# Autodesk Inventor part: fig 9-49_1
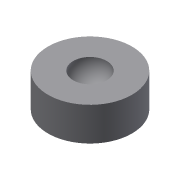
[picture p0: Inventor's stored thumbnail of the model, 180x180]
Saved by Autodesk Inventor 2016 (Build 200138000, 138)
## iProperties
Created: 2013-03
Part Number: fig 9-49_1
Material: Generic
Document SubType Name: Modeling
Designer: CADCIM
Density: 1 g/cm^3
Appearance: Default
Author: CADCIM
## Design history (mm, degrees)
sketch "Sketch1"
  geometry: C1 r 12.5 at (0, 0); 1 further point
  constraints: 1 centre point, 1 coincident
  dimensions: "d0" = 25 diameter of C1
extrude "Extrusion1" new body sketch "Sketch1" distance "d2" = 10; taper "d3" = 0 deg
sketch "Sketch2"
  geometry: L1 (12.5, 10)-(-12.5, 10) reference; L2 (-5, 10)-(5, 10); A1 r 5 centre (0, 10) between (-5, 10) and (5, 10); 1 further point
  constraints: 2 end point, 2 point on circle, 2 point on line, 1 centre point, 1 midpoint
  dimensions: "d4" = 10 diameter of A1
revolve "Revolution1" sketch "Sketch2" stored, may be unused: angle "d6" = 90 deg
body "Solid1"
